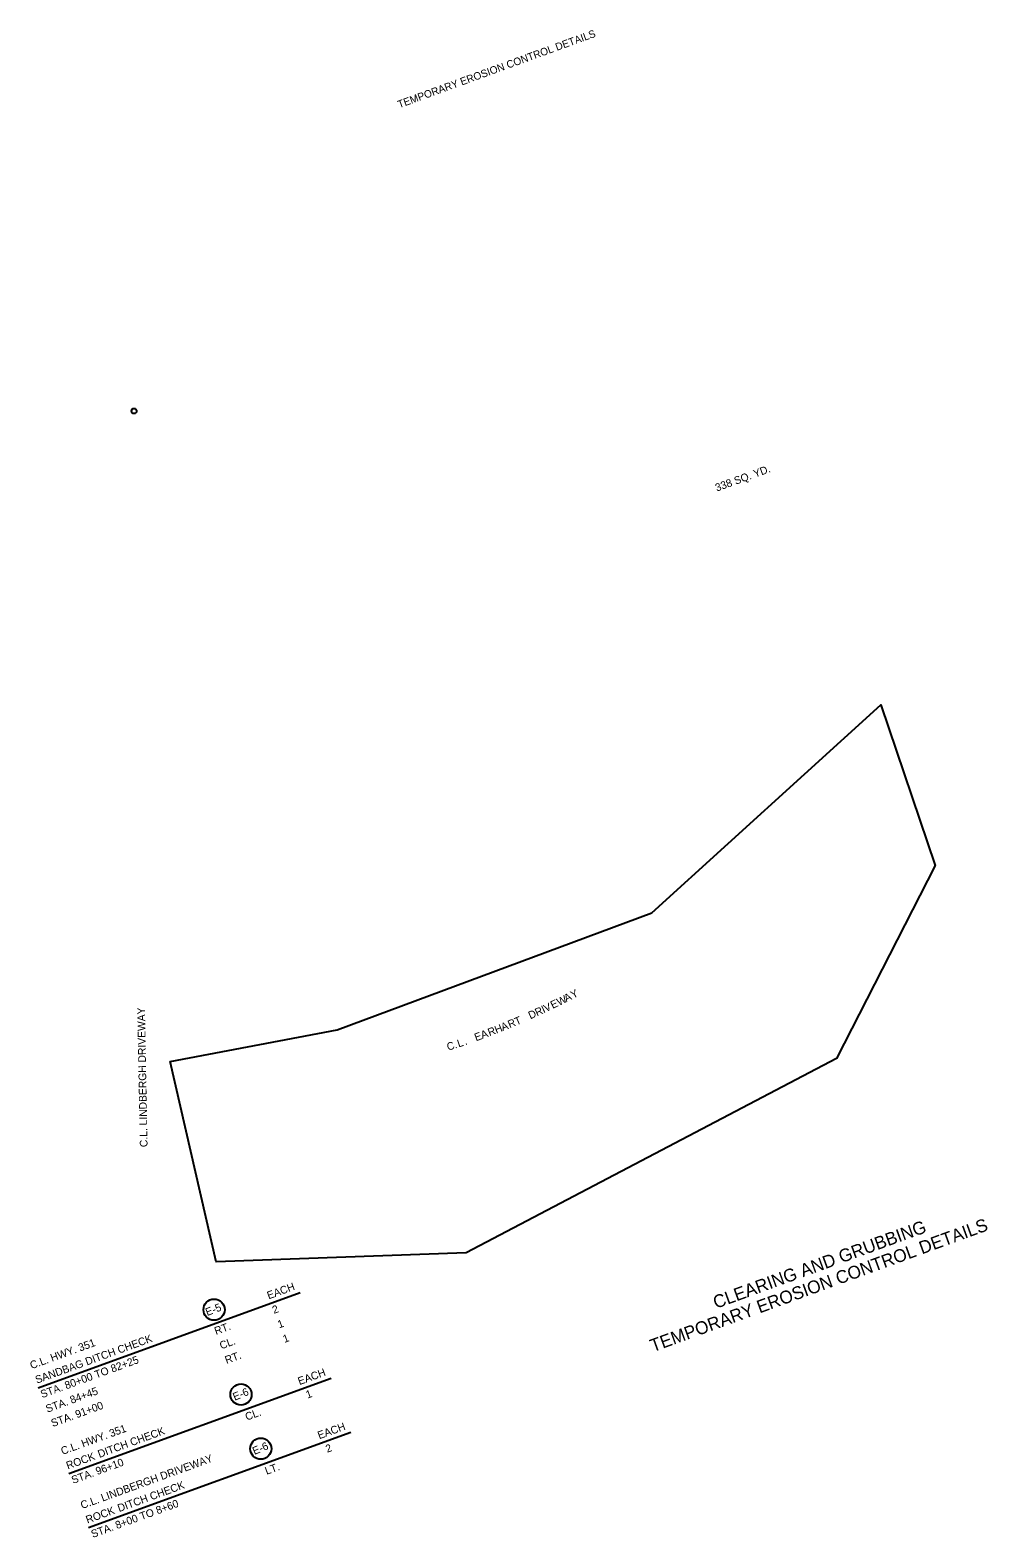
# Model space of a CAD drawing. Extents: x 1710835 to 1712392, y 548501 to 549912.
# Drawn here: x 1711646 to 1712392, y 548737 to 549912 of the extents above; entities that cross this region are included whole.
import ezdxf

# ---------------------------------------------------------------- set-up
doc = ezdxf.new("R2010")
doc.units = 0
for name, color, linetype in [('R_Annotation', 7, 'Continuous'), ('R_Border', 7, 'Continuous'), ('R_Erosion', 7, 'Continuous'), ('R_Horz Alg Annot', 7, 'Continuous'), ('R_No Plot', 7, 'Continuous')]:
    doc.layers.add(name, color=color, linetype=linetype)

msp = doc.modelspace()

# ---------------------------------------------------------------- linework, layer by layer
at = {"layer": 'R_Annotation'}
for p, q in [((1711652, 548854.3), (1711856.1, 548928.6)), ((1711676.1, 548787.5), (1711880.2, 548861.8)), ((1711691.4, 548745.3), (1711895.5, 548819.6))]:
    msp.add_line(p, q, dxfattribs=at)
at = {"layer": 'R_Erosion'}
for centre in [(1711789.1, 548915.1), (1711810.1, 548849), (1711825.5, 548806.8)]:
    msp.add_circle(centre, 8.26, dxfattribs=at)
at = {"layer": 'R_Horz Alg Annot'}
msp.add_circle((1711726.8, 549615.3), 2, dxfattribs=at)
at = {"layer": 'R_No Plot'}
msp.add_lwpolyline([(1711754.8, 549108.5), (1711885, 549133.2), (1712129.9, 549224.3), (1712308.3, 549386.5), (1712350.7, 549261.3), (1712273.9, 549110.8), (1711985.5, 548959.3), (1711790.7, 548952.3)], close=True, dxfattribs=at)

# ---------------------------------------------------------------- texts
at = {"layer": 'R_Annotation'}
for s, height, rotation, p in [('338 SQ. YD.', 6, 20, (1712180.6, 549552.5)), ('Y', 6, 27.6419, (1712068.6, 549157.3)), ('C.L. LINDBERGH DRIVEWAY', 6, 91.0787, (1711737.3, 549041.8)), ('R', 6, 24.8223, (1712040.6, 549143.6)), ('I', 6, 25.3349, (1712045.7, 549146)), ('V', 6, 25.5144, (1712047.5, 549146.8)), ('E', 6, 26.0441, (1712052.8, 549149.4)), ('W', 6, 26.5311, (1712057.7, 549151.7)), ('A', 6, 27.1121, (1712063.4, 549154.6)), ('A', 6, 22.1949, (1712013.9, 549132.1)), ('R', 6, 22.7247, (1712019.3, 549134.4)), ('T', 6, 23.2373, (1712024.6, 549136.5)), ('D', 6, 24.3096, (1712035.4, 549141.3)), ('E', 6, 20.1785, (1711993.1, 549124.2)), ('A', 6, 20.6655, (1711998.1, 549126)), ('R', 6, 21.1953, (1712003.6, 549128.1)), ('H', 6, 21.7079, (1712008.9, 549130.1)), ('C', 6, 18.1065, (1711971.4, 549116.8)), ('.', 6, 18.6192, (1711976.8, 549118.5)), ('L', 6, 18.8841, (1711979.6, 549119.4)), ('.', 6, 19.3711, (1711984.7, 549121.2)), ('TEMPORARY EROSION CONTROL DETAILS', 10, 20, (1712130.8, 548881.9)), ('CLEARING AND GRUBBING', 10, 20, (1712179.9, 548915.7)), ('EACH', 6, 20, (1711831.6, 548923.1)), ('2', 6, 20, (1711835.7, 548911.8)), ('RT. ', 6, 20, (1711790.6, 548895.4)), ('1', 6, 20, (1711839.8, 548900.5)), ('C.L. HWY. 351', 6, 20, (1711647, 548868.7)), ('SANDBAG DITCH CHECK', 6, 20, (1711651.1, 548857.4)), ('CL.', 6, 20, (1711794.7, 548884.1)), ('1', 6, 20, (1711843.9, 548889.2)), ('RT.', 6, 20, (1711798.8, 548872.8)), ('STA. 80+00 TO 82+25', 6, 20, (1711655.2, 548846.1)), ('EACH', 6, 20, (1711855.6, 548856.3)), ('STA. 84+45', 6, 20, (1711659.3, 548834.8)), (' 1', 6, 20, (1711859.7, 548845)), ('STA. 91+00', 6, 20, (1711663.4, 548823.6)), ('CL. ', 6, 20, (1711814.6, 548828.6)), ('C.L. HWY. 351', 6, 20, (1711671.1, 548801.9)), (' DITCH CHECK', 6, 20, (1711697.7, 548798.8)), ('EACH', 6, 20, (1711871, 548814.1)), (' 2', 6, 20, (1711875.1, 548802.8)), ('ROCK', 6, 20, (1711675.2, 548790.6)), ('STA. 96+10', 6, 20, (1711679.3, 548779.3)), ('C.L. LINDBERGH DRIVEWAY', 6, 20, (1711686.4, 548759.7)), ('LT. ', 6, 20, (1711830, 548786.4)), (' DITCH CHECK', 6, 20, (1711713.1, 548756.6)), ('STA. 8+00 TO 8+60', 6, 20, (1711694.6, 548737.2)), ('ROCK', 6, 20, (1711690.5, 548748.4))]:
    msp.add_text(s, height=height, rotation=rotation, dxfattribs=at).set_placement(p)
at = {"layer": 'R_Border'}
msp.add_text('TEMPORARY EROSION CONTROL DETAILS', height=5.862, rotation=20, dxfattribs=at).set_placement((1711933.3, 549851.2))
at = {"layer": 'R_Erosion'}
for s, rotation, p in [('E-5 ', 21.5359, (1711783.8, 548910.1)), ('E-6 ', 22.7601, (1711805.2, 548844.1)), ('E-6 ', 22.7601, (1711820.5, 548801.9))]:
    msp.add_text(s, height=6, rotation=rotation, dxfattribs=at).set_placement(p)

doc.saveas('drawing.dxf')
